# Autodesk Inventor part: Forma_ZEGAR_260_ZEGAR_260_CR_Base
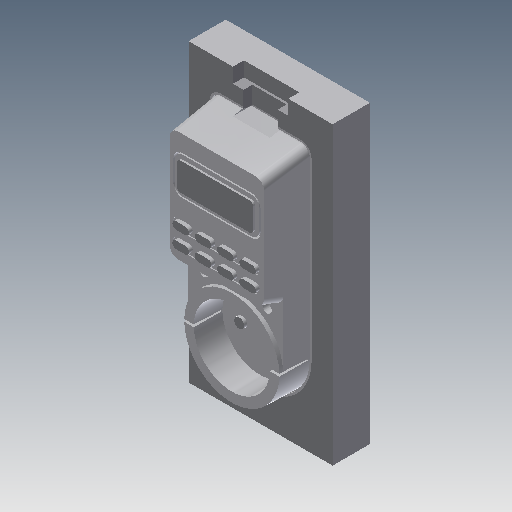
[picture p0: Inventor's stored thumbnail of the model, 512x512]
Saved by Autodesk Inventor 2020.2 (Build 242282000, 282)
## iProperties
Created: 2015-01
Part Number: Forma_ZEGAR_260_ZEGAR_260_CR_Base
Material: Ogólny
Document SubType Name: Modeling
Designer: F.Stasiak
Density: 1 g/cm^3
Appearance: Domyślna
Catalog Web Link: www.expertbooks.pl
Manager: www.cadconsulting.pl
Company: Fabian Stasiak CAD Consulting
Author: F.Stasiak
Subject: Zbiór ćwiczeń. Autodesk Inventor 2020. Kurs Professional
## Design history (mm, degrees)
node "Forma_ZEGAR_260_ZEGAR_260_MP"
feature "Rzeźbienie12"
feature "Bryła13::Forma_ZEGAR_260_ZEGAR_260_MP"
tag "Bryła wyprowadzona5"
node "Bryła5"
feature "Forma_ZEGAR_260_ZEGAR_260_MP_Bodies"
feature "Powierzchnia12"
body "Srf12"
